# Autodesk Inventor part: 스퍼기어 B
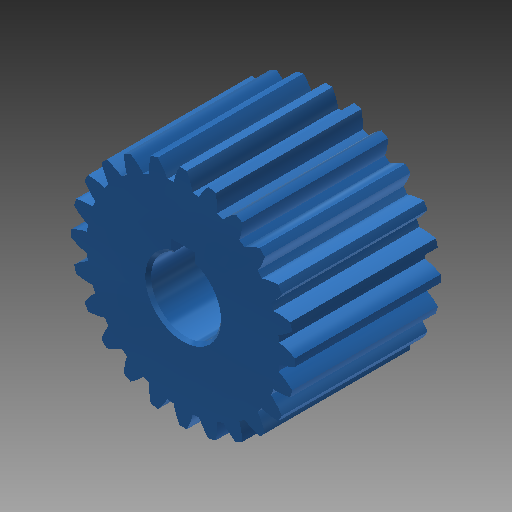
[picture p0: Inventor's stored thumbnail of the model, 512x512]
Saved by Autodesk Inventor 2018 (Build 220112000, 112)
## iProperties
Created: 2020-04
Part Number: 스퍼기어 B
Material: 강철, 연강
Document SubType Name: Modeling
Designer: mduedu
Categories: <?xml version="1.0" encoding="UTF-16"?> <MemberInstance><Categories><FamilyTemplate><FamilyTemplateParameter ValueType="xs:double" Id="1" ObjectReferenceKey="da
Density: 7.86 g/cm^3
Mass: 175.416 g
Surface Area: 76.8935 cm^2
Volume: 22.3176 cm^3
Appearance: 청록색
CustomPartVersion: 1
Author: mduedu
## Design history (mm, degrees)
sketch "Sketch1"
  geometry: C1 r 19.2 at (0, 0)
  constraints: 1 centre point
  dimensions: "d0" = 38.4 diameter of C1 (= da_da)
extrude "Extrusion1" new body sketch "Sketch1" distance "d1" = 25 (= da_b); taper "d2" = 0 deg
workplane "Work Plane2"
sketch "Sketch2"
  geometry: C1 r 19.2 at (0, 0) reference; C2 r 18 at (0, 0)
  constraints: 1 centre point, 1 coincident
  dimensions: "d3" = 36 diameter of C2 (= da_dw)
feature "피치 지름" sketch "Sketch2" dims "d4" = 10, "d5" = 0
workplane "Work Plane8"
workplane "Work Plane9"
feature "스퍼 기어" dims "da_b" = 25, "da_d" = 36, "da_aw" = 45, "da_da" = 38.4, "da_df" = 33.129, "da_dw" = 36, angle "da_beta" = 0 deg, "da_lefttooth" = 0, "da_righttooth" = 0
sketch "스케치3"
  geometry: L1 (-2, 5.657)-(2, 5.657); L2 (2, 5.657)-(2, 7.8); L3 (2, 7.8)-(-2, 7.8); L4 (-2, 7.8)-(-2, 5.657); A1 r 6 centre (0, 0) between (-2, 5.657) and (2, 5.657); 1 further point
  constraints: 8 end point, 2 parallel, 2 point on circle, 1 centre point, 1 coincident, 1 horizontal, 1 perpendicular
  dimensions: "d49" = 12 diameter of A1; "d51" = 4 distance of L2.end L3.end; "d52" = 13.8 dimension on A1 L3
extrude "돌출2" cut sketch "스케치3" extent not by distance; stored distance "d53" = 10; taper "d54" = 0 deg
chamfer "모따기1" distance "d55" = 0.5; stored, may be unused: second distance "d56" = 2, angle "d57" = 45 deg
body "Solid1"
body "Srf1"
other parameters: "d16" = 45 (= da_aw), "d17" = 0, "d34" = 7.5 deg (computed from da_z), "d39" = 0, "d41" = 0, "d43" = 45 (= da_aw), "d46" = 45 (= da_aw), "d47" = 0, "d48" = 0
